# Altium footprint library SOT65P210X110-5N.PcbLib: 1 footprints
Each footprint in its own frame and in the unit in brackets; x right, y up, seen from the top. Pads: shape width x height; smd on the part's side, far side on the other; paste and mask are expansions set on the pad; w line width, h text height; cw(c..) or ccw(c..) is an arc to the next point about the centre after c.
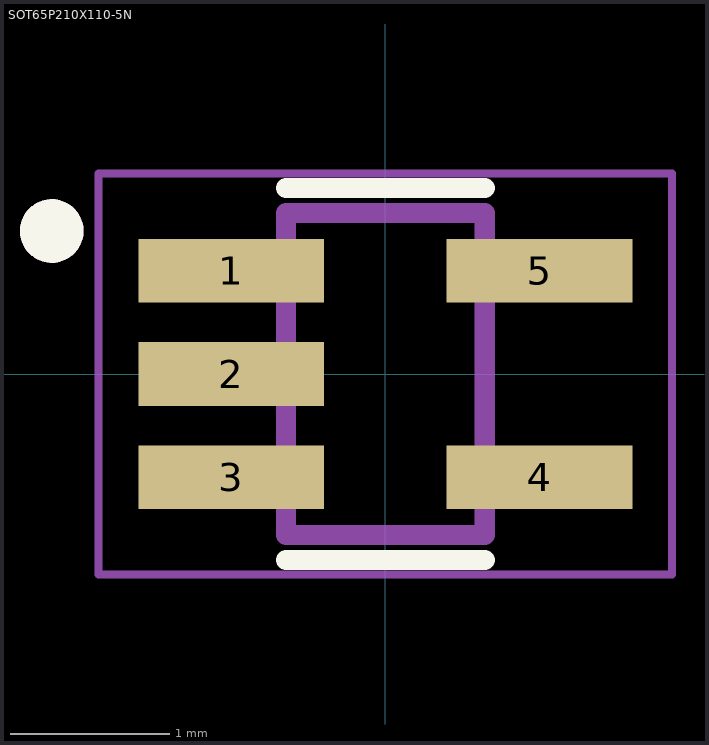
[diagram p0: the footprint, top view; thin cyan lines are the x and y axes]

## SOT65P210X110-5N [mm]
height 1.1
pads (5):
  rect 1.17x0.4 smd: 1(-0.97,0.65) 2(-0.97,0) 3(-0.97,-0.65) 4(0.97,-0.65) 5(0.97,0.65)
Top Overlay:
  circle w0.2: c-2.1,0.9 r0.1
  lines w0.127: -0.625,-1.17 0.625,-1.17 ; -0.625,1.17 0.625,1.17
Assembly Top:
  circle w0.2: c-2.1,0.9 r0.1
  lines w0.127: -0.625,-1.012 -0.625,1.012 0.625,1.012 0.625,-1.012 -0.625,-1.012
Courtyard Top:
  lines w0.05: -1.805,-1.262 -1.805,1.262 1.805,1.262 1.805,-1.262 -1.805,-1.262
3D body "step_temp.STEP": height 1.1, standoff 0, extent -1.05,-1 1.05,1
